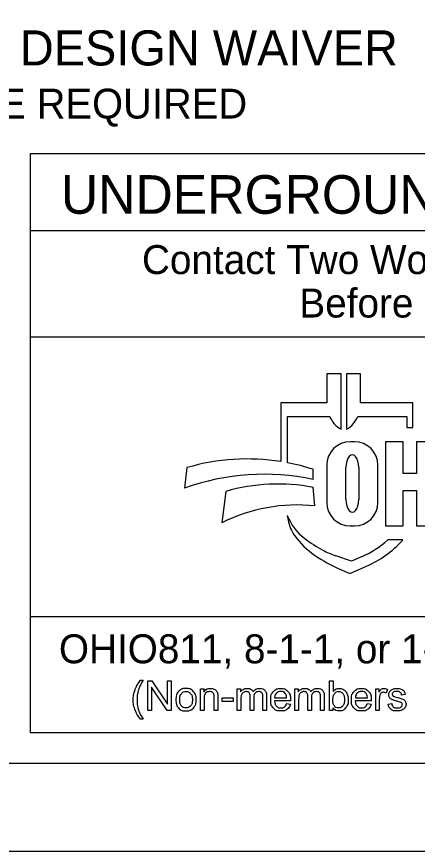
# Model space of a CAD drawing. Extents: x 0 to 34, y 0 to 22.
# Drawn here: x 3.144 to 5.428, y 0 to 4.754 of the extents above; entities that cross this region are included whole.
import ezdxf

# ---------------------------------------------------------------- set-up
doc = ezdxf.new("R2010")
doc.units = 0
for name, color, linetype in [('SH_Border', 7, 'Continuous'), ('SH_Cut_Line', 7, 'Continuous'), ('SH_Data', 7, 'Continuous')]:
    doc.layers.add(name, color=color, linetype=linetype)

msp = doc.modelspace()

# ---------------------------------------------------------------- linework, layer by layer
at = {"layer": 'SH_Border'}
msp.add_lwpolyline([(2, 21.5), (33.5, 21.5), (33.5, 0.5), (2, 0.5)], close=True, dxfattribs=at)
at = {"layer": 'SH_Cut_Line'}
msp.add_lwpolyline([(0, 0), (34, 0), (34, 22), (0, 22)], close=True, dxfattribs=at)
at = {"layer": 'SH_Data'}
for p, q in [((3.224, 3.975), (8.449, 3.975)), ((3.224, 0.675), (3.224, 3.975)), ((3.224, 3.535), (8.449, 3.535)), ((3.224, 2.93), (8.449, 2.93)), ((4.993, 2.7205), (4.9129, 2.7205)), ((4.9129, 2.7205), (4.9129, 2.554)), ((4.993, 2.4037), (4.993, 2.7205)), ((5.1042, 2.7205), (5.0241, 2.7205)), ((5.0241, 2.7205), (5.0241, 2.4037)), ((5.1042, 2.554), (5.1042, 2.7205)), ((4.9129, 2.554), (4.65, 2.554)), ((4.65, 2.554), (4.65, 2.2195)), ((5.4018, 2.554), (5.1042, 2.554)), ((5.4018, 2.4138), (5.4018, 2.554)), ((4.6877, 2.2129), (4.6877, 2.4771)), ((4.6877, 2.4771), (4.9284, 2.4771)), ((5.0886, 2.4771), (5.367, 2.4771)), ((5.367, 2.4771), (5.367, 2.4138)), ((5.367, 2.4138), (5.4018, 2.4138)), ((5.0697, 2.3328), (5.045, 2.3328)), ((5.3476, 2.3313), (5.246, 2.3313)), ((5.246, 2.3313), (5.246, 1.8533)), ((4.9113, 2.1991), (4.9113, 1.987)), ((5.0202, 2.004), (5.0202, 2.1867)), ((5.0946, 2.1867), (5.0946, 2.004)), ((5.2033, 1.987), (5.2033, 2.1991)), ((4.1149, 2.1853), (4.1009, 2.0686)), ((4.8339, 2.1176), (4.8339, 2.1756)), ((4.3355, 2.0501), (4.3136, 1.8706)), ((4.844, 1.9671), (4.8347, 2.0731)), ((5.3476, 1.8533), (5.3476, 2.0554)), ((4.6867, 1.9134), (4.6913, 1.8867)), ((5.045, 1.8533), (5.0697, 1.8533)), ((5.246, 1.8533), (5.3476, 1.8533)), ((5.3452, 1.7733), (5.2594, 1.7733)), ((5.3428, 1.7707), (5.3452, 1.7733)), ((5.0517, 1.6525), (4.963, 1.6831)), ((5.113, 1.6791), (5.0517, 1.6525)), ((5.0427, 1.5823), (5.1373, 1.6233)), ((4.9869, 1.6068), (5.0427, 1.5823)), ((8.449, 1.3351), (3.224, 1.3351)), ((8.449, 0.675), (3.224, 0.675))]:
    msp.add_line(p, q, dxfattribs=at)
for points in [[(5.3476, 2.0554), (5.4237, 2.0554), (5.4237, 1.8533), (5.5252, 1.8533), (5.5252, 2.3313), (5.4237, 2.3313), (5.4237, 2.151), (5.3476, 2.151), (5.3476, 2.3313)], [(3.8498, 0.9742), (3.8647, 0.9742)], [(3.8913, 0.8019), (3.8913, 0.9713), (3.9142, 0.9713), (4.0034, 0.8383), (4.0034, 0.9713), (4.0248, 0.9713), (4.0248, 0.8019), (4.0019, 0.8019), (3.9127, 0.935), (3.9127, 0.8019), (3.8913, 0.8019)], [(4.9467, 0.8019), (4.9274, 0.8019), (4.9274, 0.9713), (4.9482, 0.9713), (4.9482, 0.911)], [(4.1914, 0.8019), (4.1914, 0.9247), (4.2101, 0.9247), (4.2101, 0.9073)], [(4.4017, 0.8019), (4.4017, 0.9247), (4.4203, 0.9247), (4.4203, 0.9074)], [(4.7304, 0.8019), (4.7304, 0.9247), (4.749, 0.9247), (4.749, 0.9074)], [(5.1905, 0.8019), (5.1905, 0.9247), (5.2092, 0.9247), (5.2092, 0.9061)], [(5.2571, 0.9208), (5.2498, 0.9015)], [(4.2121, 0.8689), (4.2121, 0.8019), (4.1914, 0.8019)], [(4.291, 0.8774), (4.291, 0.8019), (4.2702, 0.8019), (4.2702, 0.8765)], [(4.3147, 0.8528), (4.3147, 0.8737), (4.3787, 0.8737), (4.3787, 0.8528), (4.3147, 0.8528)], [(4.4225, 0.8656), (4.4225, 0.8019), (4.4017, 0.8019)], [(4.4954, 0.8732), (4.4954, 0.8019), (4.4746, 0.8019), (4.4746, 0.8816)], [(4.5681, 0.8862), (4.5681, 0.8019), (4.5473, 0.8019), (4.5473, 0.8792)], [(4.7049, 0.858), (4.6133, 0.858)], [(4.6145, 0.875), (4.683, 0.875)], [(4.7512, 0.8656), (4.7512, 0.8019), (4.7304, 0.8019)], [(4.8241, 0.8732), (4.8241, 0.8019), (4.8033, 0.8019), (4.8033, 0.8816)], [(4.8968, 0.8862), (4.8968, 0.8019), (4.876, 0.8019), (4.876, 0.8792)], [(5.1652, 0.858), (5.0736, 0.858)], [(5.0748, 0.875), (5.1433, 0.875)], [(5.2112, 0.8662), (5.2112, 0.8019), (5.1905, 0.8019)], [(5.3586, 0.893), (5.3382, 0.8902)], [(4.6828, 0.8416), (4.7043, 0.8389)], [(4.9467, 0.8173), (4.9467, 0.8019)], [(5.1431, 0.8416), (5.1646, 0.8389)], [(5.2611, 0.8386), (5.2816, 0.8418)], [(3.8647, 0.7521), (3.8498, 0.7521)]]:
    msp.add_lwpolyline(points, dxfattribs=at)
for centre, radius, start, end in [((5.0649, 2.5321), 0.1471, 201.9296, 240.7469), ((4.9522, 2.5321), 0.1471, 299.2531, 338.0704), ((5.045, 2.1991), 0.1337, 90, 180), ((5.0697, 2.1991), 0.1337, 0, 90), ((4.4586, 1.0111), 1.2235, 81.0007, 106.3144), ((4.4586, 1.0111), 1.2235, 72.1402, 79.2074), ((4.5528, 0.8152), 1.3324, 77.8238, 109.8274), ((4.6342, 0.9979), 1.0937, 79.44, 105.8467), ((4.7418, 1.023), 0.9496, 83.8248, 116.8021), ((5.045, 1.987), 0.1337, 180, 270), ((5.0697, 1.987), 0.1337, 270, 0), ((4.9667, 2.0211), 0.2999, 201.0457, 232.5314), ((4.9024, 1.9227), 0.2141, 189.6817, 216.0884), ((5.1021, 2.0682), 0.4612, 216.0884, 235.7167), ((5.2543, 2.3964), 0.7728, 232.5314, 241.794), ((4.8988, 2.1728), 0.5381, 293.4582, 312.0712), ((4.8988, 2.1728), 0.599, 293.4582, 317.8286), ((5.127, 2.1592), 0.5035, 241.794, 250.9821), ((5.3508, 2.4331), 0.9028, 235.7167, 246.2325)]:
    msp.add_arc(centre, radius, start, end, dxfattribs=at)
for centre, start_param, end_param in [((5.0574, 2.1867), 4.712389, 7.853982), ((5.0574, 2.004), 1.570796, 4.712389)]:
    msp.add_ellipse(centre, major_axis=(0, 0.0723), ratio=0.514403, start_param=start_param, end_param=end_param, dxfattribs=at)
for points in [[(3.8498, 0.7521), (3.8326, 0.7738), (3.8207, 0.8029), (3.8088, 0.832), (3.8088, 0.8632), (3.8088, 0.8907), (3.8177, 0.9159), (3.8281, 0.9452), (3.8498, 0.9742)], [(3.8647, 0.9742), (3.8507, 0.9501), (3.8462, 0.9399), (3.8392, 0.9239), (3.8352, 0.9066), (3.8302, 0.885), (3.8302, 0.8631), (3.8302, 0.8075), (3.8647, 0.7521)], [(4.052, 0.8633), (4.052, 0.8974), (4.071, 0.9138), (4.0868, 0.9274), (4.1096, 0.9274), (4.1349, 0.9274), (4.1509, 0.9109), (4.167, 0.8943), (4.167, 0.8651), (4.167, 0.8414), (4.1599, 0.8278), (4.1528, 0.8142), (4.1392, 0.8067), (4.1256, 0.7992), (4.1096, 0.7992), (4.0838, 0.7992), (4.0679, 0.8157), (4.052, 0.8323), (4.052, 0.8633)], [(4.0735, 0.8633), (4.0735, 0.8397), (4.0837, 0.828), (4.094, 0.8163), (4.1096, 0.8163), (4.125, 0.8163), (4.1353, 0.8281), (4.1455, 0.8398), (4.1455, 0.864), (4.1455, 0.8868), (4.1352, 0.8985), (4.1249, 0.9103), (4.1096, 0.9103), (4.094, 0.9103), (4.0837, 0.8986), (4.0735, 0.8869), (4.0735, 0.8633)], [(4.2101, 0.9073), (4.2236, 0.9274), (4.2491, 0.9274), (4.2602, 0.9274), (4.2695, 0.9234), (4.2788, 0.9195), (4.2834, 0.913), (4.288, 0.9065), (4.2899, 0.8976), (4.291, 0.8918), (4.291, 0.8774)], [(4.2702, 0.8765), (4.2702, 0.8893), (4.2678, 0.8955), (4.2654, 0.9018), (4.2592, 0.9056), (4.253, 0.9094), (4.2447, 0.9094), (4.2314, 0.9094), (4.2218, 0.9009), (4.2121, 0.8925), (4.2121, 0.8689)], [(4.4203, 0.9074), (4.426, 0.9164), (4.4356, 0.9219), (4.4452, 0.9274), (4.4575, 0.9274), (4.4711, 0.9274), (4.4799, 0.9218), (4.4886, 0.9161), (4.4922, 0.9059), (4.5068, 0.9274), (4.5301, 0.9274), (4.5484, 0.9274), (4.5583, 0.9173), (4.5681, 0.9072), (4.5681, 0.8862)], [(4.4746, 0.8816), (4.4746, 0.8955), (4.4695, 0.9024), (4.4644, 0.9094), (4.4529, 0.9094), (4.4441, 0.9094), (4.4366, 0.9047), (4.4292, 0.9001), (4.4258, 0.8912), (4.4225, 0.8823), (4.4225, 0.8656)], [(4.5473, 0.8792), (4.5473, 0.8917), (4.5453, 0.8972), (4.5433, 0.9027), (4.5379, 0.906), (4.5326, 0.9094), (4.5255, 0.9094), (4.5125, 0.9094), (4.504, 0.9007), (4.4954, 0.8921), (4.4954, 0.8732)], [(4.7043, 0.8389), (4.6992, 0.82), (4.6855, 0.8096), (4.6717, 0.7992), (4.6503, 0.7992), (4.6234, 0.7992), (4.6076, 0.8158), (4.5919, 0.8324), (4.5919, 0.8623), (4.5919, 0.8932), (4.6078, 0.9103), (4.6238, 0.9274), (4.6492, 0.9274), (4.6738, 0.9274), (4.6894, 0.9107), (4.705, 0.8939), (4.705, 0.8635), (4.705, 0.8617), (4.7049, 0.858)], [(4.683, 0.875), (4.6816, 0.8905), (4.6752, 0.8983), (4.6652, 0.9104), (4.6494, 0.9104), (4.6351, 0.9104), (4.6253, 0.9008), (4.6155, 0.8911), (4.6145, 0.875)], [(4.749, 0.9074), (4.7548, 0.9164), (4.7644, 0.9219), (4.774, 0.9274), (4.7862, 0.9274), (4.7999, 0.9274), (4.8086, 0.9218), (4.8173, 0.9161), (4.8209, 0.9059), (4.8355, 0.9274), (4.8589, 0.9274), (4.8771, 0.9274), (4.887, 0.9173), (4.8968, 0.9072), (4.8968, 0.8862)], [(4.8033, 0.8816), (4.8033, 0.8955), (4.7983, 0.9024), (4.7932, 0.9094), (4.7816, 0.9094), (4.7728, 0.9094), (4.7654, 0.9047), (4.7579, 0.9001), (4.7545, 0.8912), (4.7512, 0.8823), (4.7512, 0.8656)], [(4.876, 0.8792), (4.876, 0.8917), (4.874, 0.8972), (4.872, 0.9027), (4.8667, 0.906), (4.8614, 0.9094), (4.8542, 0.9094), (4.8412, 0.9094), (4.8327, 0.9007), (4.8241, 0.8921), (4.8241, 0.8732)], [(4.9464, 0.8642), (4.9464, 0.8422), (4.9524, 0.8323), (4.9622, 0.8163), (4.979, 0.8163), (4.9926, 0.8163), (5.0025, 0.8281), (5.0124, 0.84), (5.0124, 0.8634), (5.0124, 0.8875), (5.0029, 0.8989), (4.9934, 0.9104), (4.9799, 0.9104), (4.9663, 0.9104), (4.9563, 0.8985), (4.9464, 0.8867), (4.9464, 0.8642)], [(4.9482, 0.911), (4.9614, 0.9274), (4.9819, 0.9274), (4.9932, 0.9274), (5.0033, 0.9229), (5.0134, 0.9183), (5.0199, 0.91), (5.0264, 0.9018), (5.0301, 0.8901), (5.0338, 0.8785), (5.0338, 0.8652), (5.0338, 0.8336), (5.0182, 0.8164), (5.0026, 0.7992), (4.9808, 0.7992), (4.9591, 0.7992), (4.9467, 0.8173)], [(5.1646, 0.8389), (5.1595, 0.82), (5.1458, 0.8096), (5.132, 0.7992), (5.1106, 0.7992), (5.0837, 0.7992), (5.0679, 0.8158), (5.0522, 0.8324), (5.0522, 0.8623), (5.0522, 0.8932), (5.0681, 0.9103), (5.0841, 0.9274), (5.1095, 0.9274), (5.1341, 0.9274), (5.1497, 0.9107), (5.1653, 0.8939), (5.1653, 0.8635), (5.1653, 0.8617), (5.1652, 0.858)], [(5.1433, 0.875), (5.1419, 0.8905), (5.1355, 0.8983), (5.1255, 0.9104), (5.1097, 0.9104), (5.0953, 0.9104), (5.0856, 0.9008), (5.0758, 0.8911), (5.0748, 0.875)], [(5.2092, 0.9061), (5.2163, 0.9191), (5.2224, 0.9233), (5.2285, 0.9274), (5.2357, 0.9274), (5.2462, 0.9274), (5.2571, 0.9208)], [(5.2498, 0.9015), (5.2422, 0.906), (5.2346, 0.906), (5.2278, 0.906), (5.2224, 0.9019), (5.217, 0.8978), (5.2147, 0.8905), (5.2112, 0.8794), (5.2112, 0.8662)], [(5.3382, 0.8902), (5.3368, 0.8997), (5.3301, 0.9051), (5.3235, 0.9104), (5.3113, 0.9104), (5.297, 0.9104), (5.2908, 0.9056), (5.2847, 0.9009), (5.2847, 0.8945), (5.2847, 0.8905), (5.2873, 0.8872), (5.2898, 0.8839), (5.2952, 0.8817), (5.2984, 0.8805), (5.3136, 0.8763), (5.3357, 0.8705), (5.3445, 0.8667), (5.3532, 0.863), (5.3582, 0.8558), (5.3632, 0.8486), (5.3632, 0.838), (5.3632, 0.8276), (5.3571, 0.8184), (5.3511, 0.8093), (5.3396, 0.8042), (5.3281, 0.7992), (5.3137, 0.7992), (5.2897, 0.7992), (5.2771, 0.8091), (5.2646, 0.8191), (5.2611, 0.8386)], [(5.2816, 0.8418), (5.2834, 0.8294), (5.2913, 0.8229), (5.2992, 0.8163), (5.3135, 0.8163), (5.3279, 0.8163), (5.3348, 0.8221), (5.3418, 0.8279), (5.3418, 0.8358), (5.3418, 0.8429), (5.3356, 0.8469), (5.3313, 0.8497), (5.3143, 0.854), (5.2914, 0.8598), (5.2826, 0.864), (5.2737, 0.8682), (5.2691, 0.8756), (5.2646, 0.8831), (5.2646, 0.8921), (5.2646, 0.9003), (5.2683, 0.9073), (5.2721, 0.9143), (5.2786, 0.9189), (5.2834, 0.9225), (5.2918, 0.9249), (5.3002, 0.9274), (5.3098, 0.9274), (5.3243, 0.9274), (5.3352, 0.9233), (5.3462, 0.9191), (5.3514, 0.912), (5.3566, 0.9049), (5.3586, 0.893)], [(4.6133, 0.858), (4.6145, 0.8377), (4.6248, 0.827), (4.635, 0.8163), (4.6504, 0.8163), (4.6619, 0.8163), (4.67, 0.8223), (4.6781, 0.8283), (4.6828, 0.8416)], [(5.0736, 0.858), (5.0748, 0.8377), (5.0851, 0.827), (5.0953, 0.8163), (5.1107, 0.8163), (5.1222, 0.8163), (5.1303, 0.8223), (5.1384, 0.8283), (5.1431, 0.8416)]]:
    msp.add_open_spline(points, degree=3, dxfattribs=at)

# ---------------------------------------------------------------- texts
for s, height, p in [('ADA DESIGN WAIVER', 0.2, (2.5382, 4.4759)), ('NONE REQUIRED', 0.17, (2.5382, 4.1736)), ('UNDERGROUND UTILITIES', 0.22, (3.3966, 3.6311)), ('Contact Two Working Days', 0.165, (3.8584, 3.2877)), ('Before You Dig', 0.165, (4.7555, 3.0402)), ('OHIO811, 8-1-1, or 1-800-362-2764', 0.165, (3.3851, 1.0708))]:
    msp.add_text(s, height=height, dxfattribs=at).set_placement(p)

doc.saveas('drawing.dxf')
